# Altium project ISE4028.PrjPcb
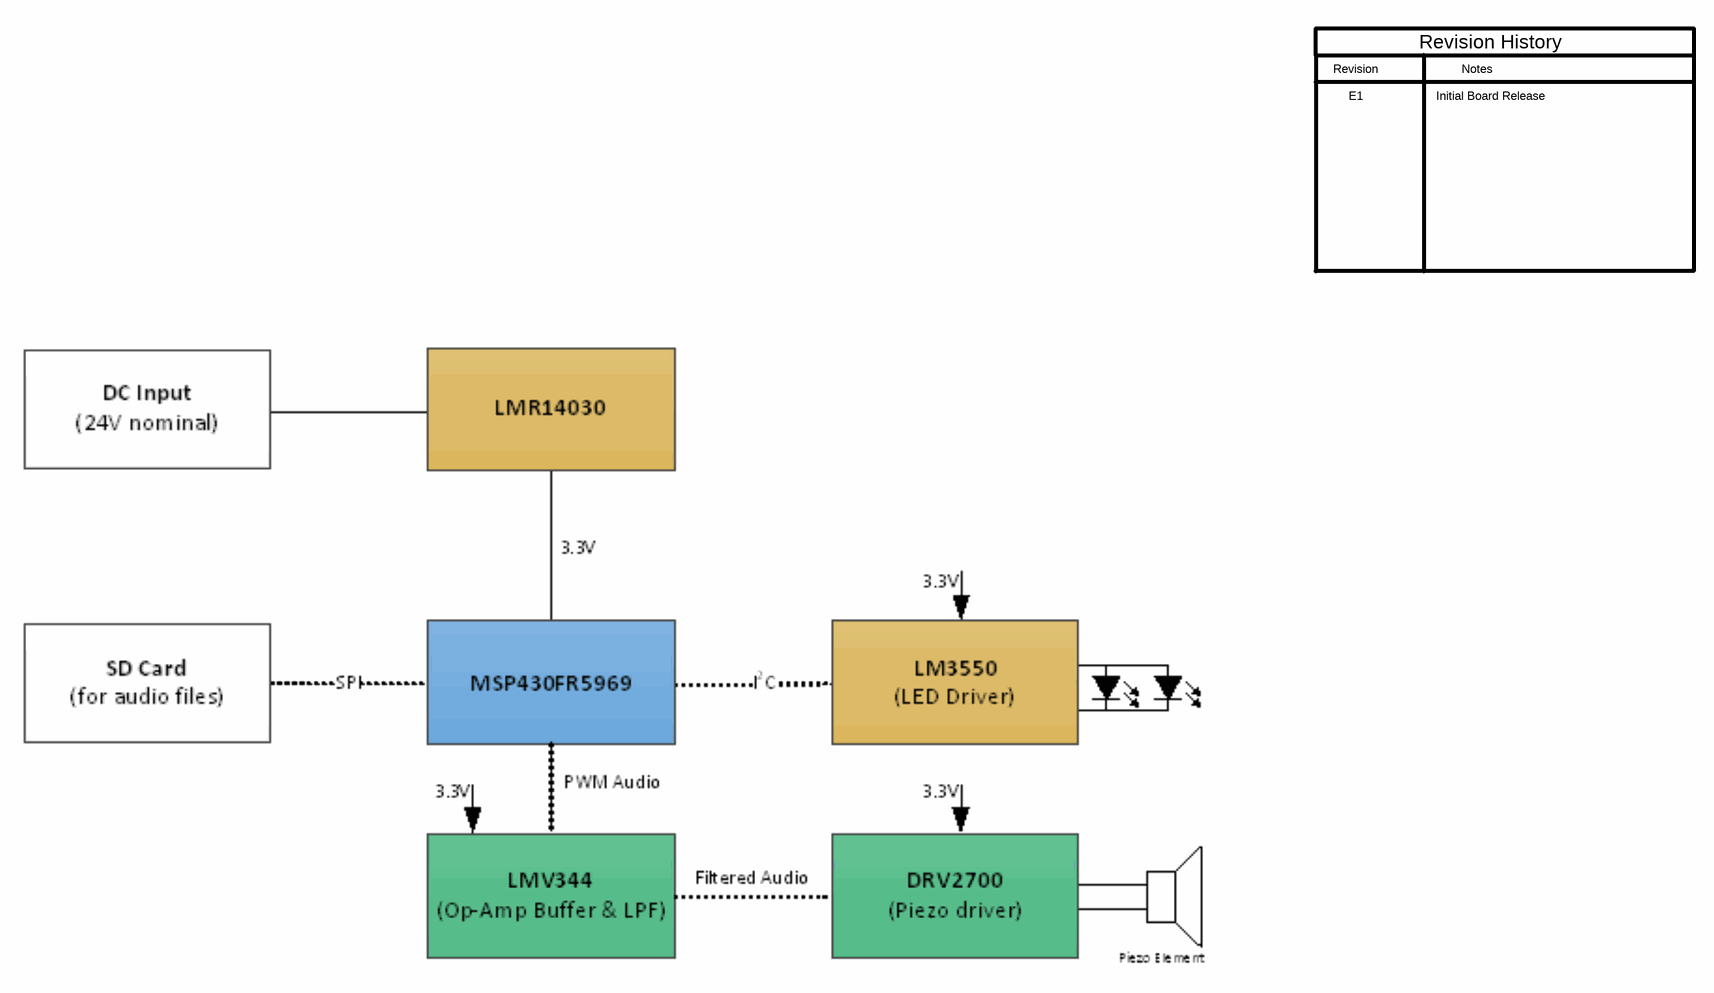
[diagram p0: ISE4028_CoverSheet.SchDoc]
CopyrightYear: 2015; EVM_Orderable: N/A; PCB_Rev: E1; PRJ_Customer: Public Release; PRJ_Engineer: Evan Cornell; PRJ_Number: ISE4028; PRJ_Title: Piezo Speaker Strobe Notification Reference Design for Fire Alarms; SCH_Rev: E1; TechSupport: http://www.ti.com/support; TID: TIDA-00376
4 sheets, 158 parts. Net scope: global (net labels, ports and power ports of the same name join across sheets).
Board file: ISE4028_TID.PcbDoc
Sheets:
  ISE4028_CoverSheet.SchDoc
  ISE4028_PWR_MCU.SchDoc
  ISE4028_PIEZO_LED.SchDoc
  ISE4028_TID_Hardware.SchDoc

## Sheet ISE4028_CoverSheet.SchDoc: CoverSheet
size 431 x 279 mm; Date: Not shown in title block; ApprovedBy: Not shown in title block; CheckedBy: Not shown in title block; Author: Not shown in title block; CompanyName: Not shown in title block; DrawnBy: Evan Cornell; Engineer: Not shown in title block; Organization: Not shown in title block; Address1: Not shown in title block; Address2: Not shown in title block; Address3: Not shown in title block; Address4: Not shown in title block; DocumentNumber: 1; Revision: Use project parameter SCH_Rev; SheetNumber: 1; SheetTotal: 4; PageSetup: Record=PageOptions¦CenterHorizontal=True¦CenterVertical=True¦PrintScale=1.00¦XCorrection=1.00¦YCorrection=1.00¦PrintKind=0¦BorderSize=5000000¦LeftOffset=0¦BottomOffset=0¦Orientation=2¦PaperLength=1000¦PaperWidth=1000¦Scale=100¦PaperSource=15¦PrintQuality=600¦MediaType=1¦DitherType=10¦PaperKind=Letter¦PrintScaleMode=1

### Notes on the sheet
- Revision
- Notes
- Revision History
- E1
- Initial Board Release

## Sheet ISE4028_PWR_MCU.SchDoc: PWR_MCU
size 431 x 279 mm; Date: Not shown in title block; ApprovedBy: Not shown in title block; CheckedBy: Not shown in title block; Author: Not shown in title block; CompanyName: Not shown in title block; DrawnBy: Evan Cornell; Engineer: Not shown in title block; Organization: Not shown in title block; Address1: Not shown in title block; Address2: Not shown in title block; Address3: Not shown in title block; Address4: Not shown in title block; DocumentNumber: 2; Revision: Use project parameter SCH_Rev; SheetNumber: 2; SheetTotal: 4; PageSetup: Record=PageOptions¦CenterHorizontal=True¦CenterVertical=True¦PrintScale=1.00¦XCorrection=1.00¦YCorrection=1.00¦PrintKind=0¦BorderSize=5000000¦LeftOffset=0¦BottomOffset=0¦Orientation=2¦PaperLength=1000¦PaperWidth=1000¦Scale=100¦PaperSource=15¦PrintQuality=600¦MediaType=1¦DitherType=10¦PaperKind=Letter¦PrintScaleMode=1
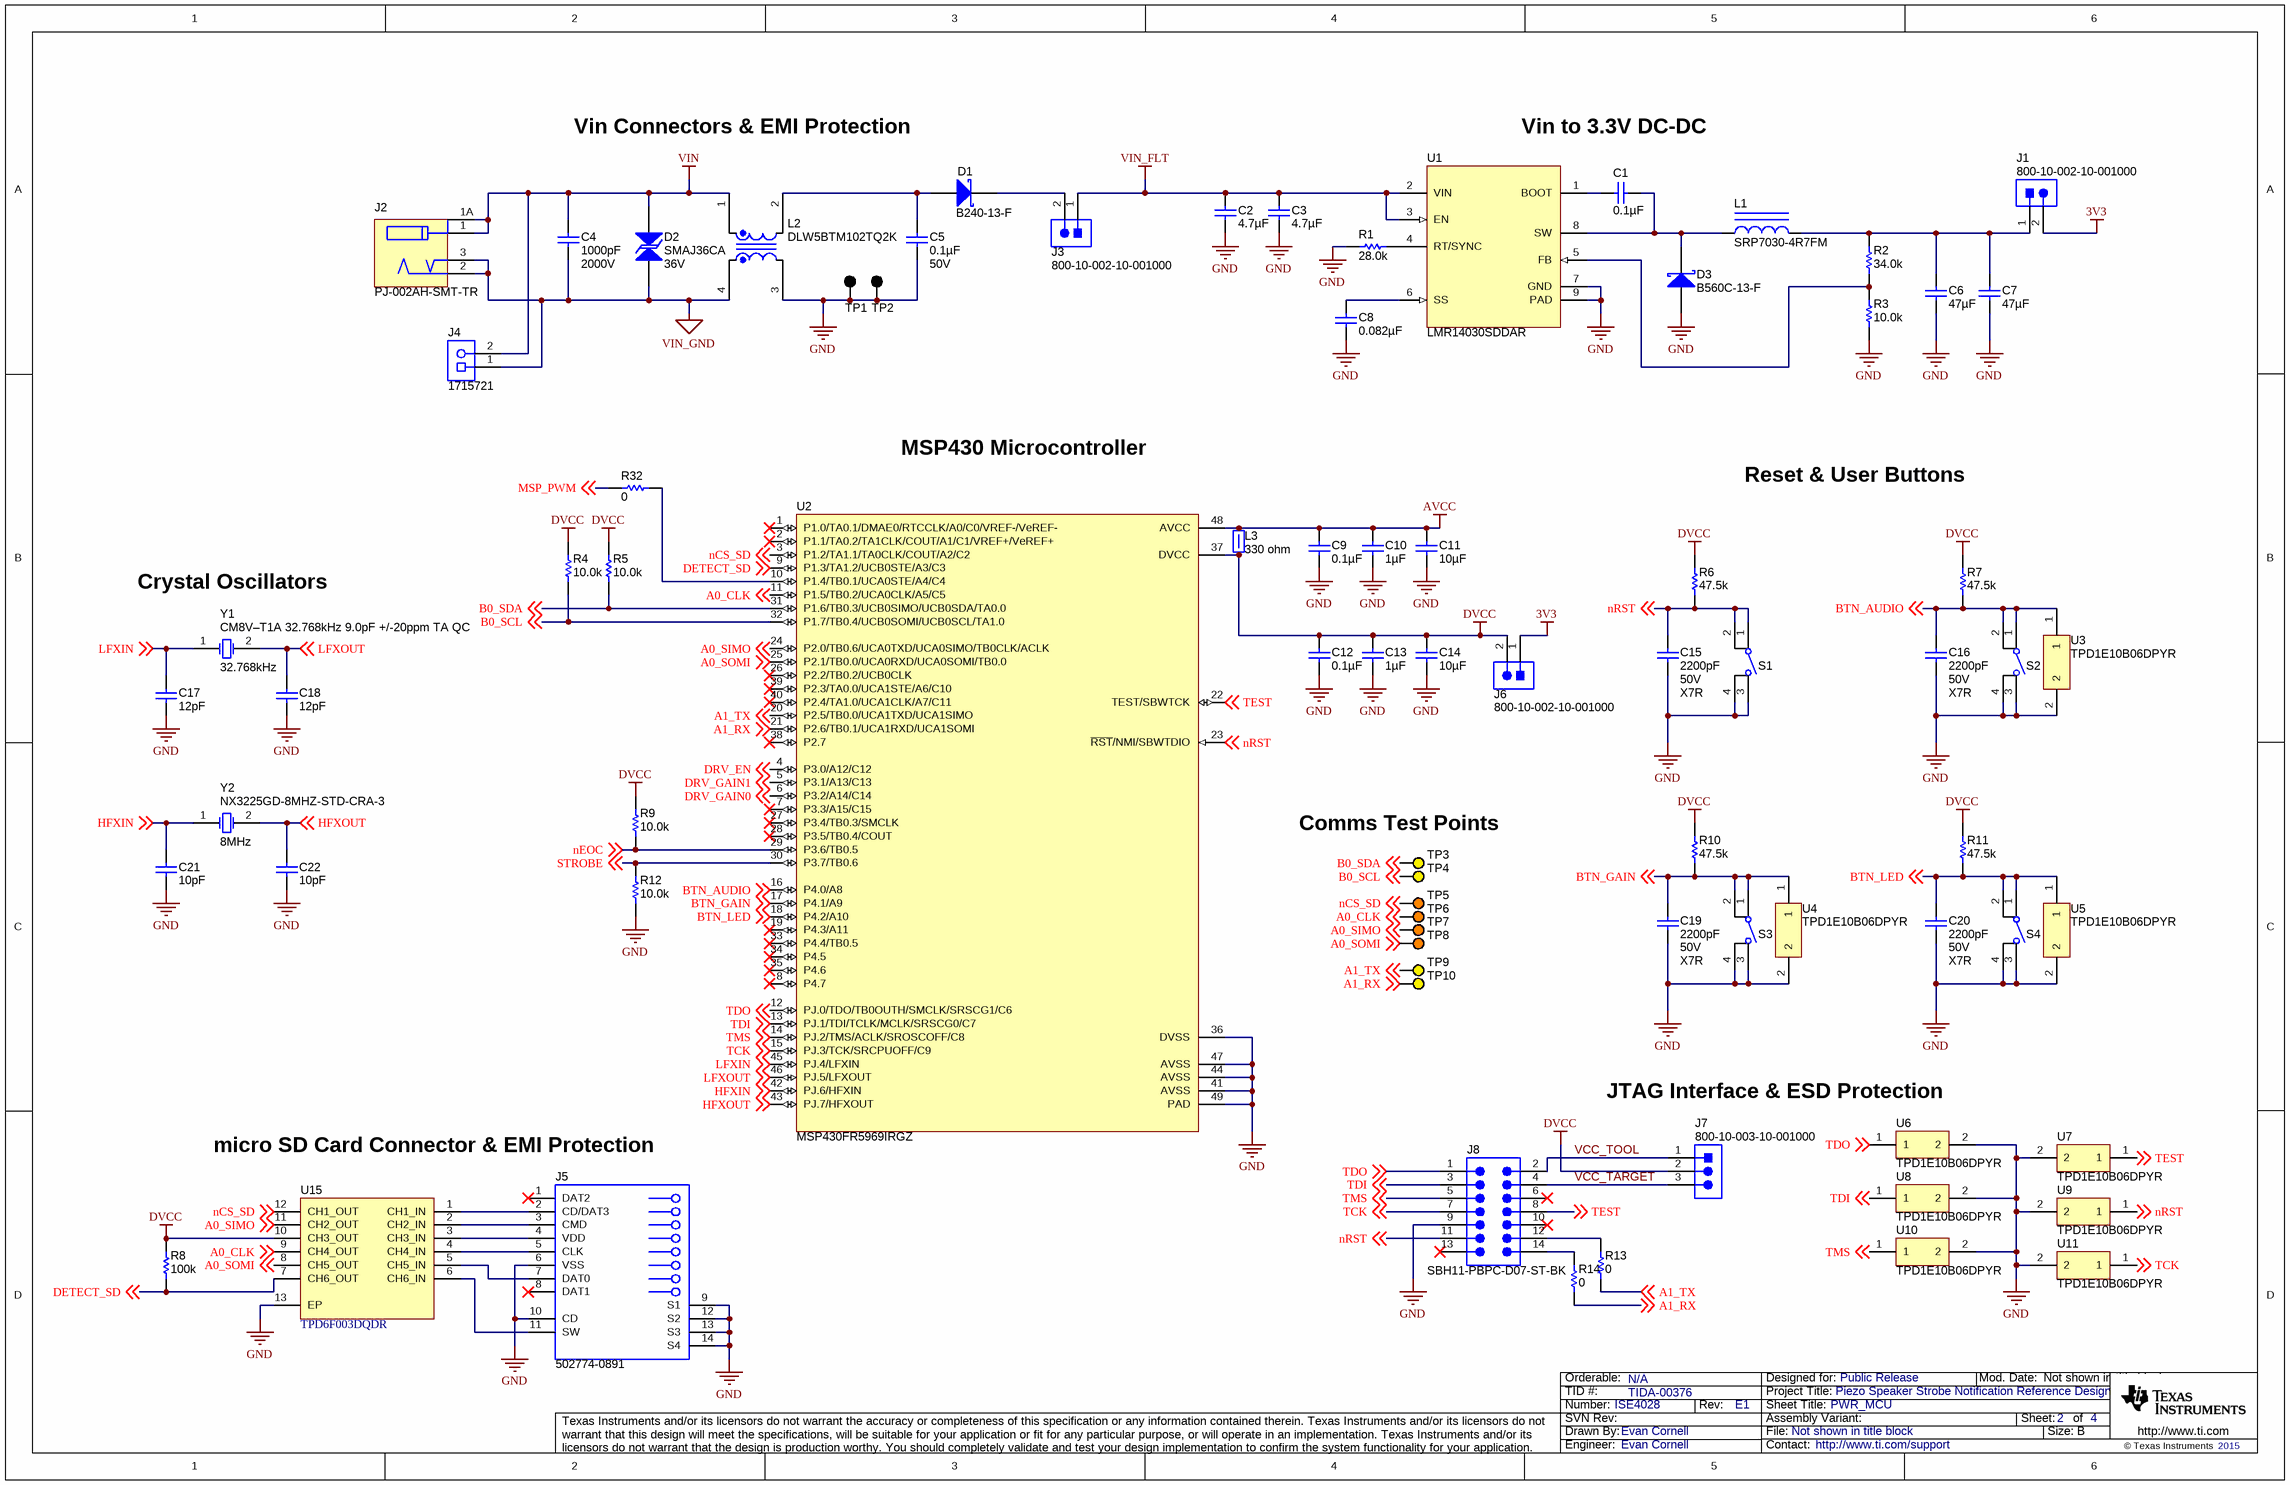
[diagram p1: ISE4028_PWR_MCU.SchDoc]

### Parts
C1  ValueDisplayed: 0.1µF  [0402]  (hidden comment: C1005X7R1H104K)
C2  ValueDisplayed: 4.7µF  [1206]  (hidden comment: GRM31CR71H475KA12L)
C3  ValueDisplayed: 4.7µF  [1206]  (hidden comment: GRM31CR71H475KA12L)
C4  ValueDisplayed: 1000pF  Value2: 2000V  [1210]  (hidden comment: C1210C102KGRACTU)
C5  ValueDisplayed: 0.1µF  Value2: 50V  [0402]  (hidden comment: C1005X7R1H104K)
C6  ValueDisplayed: 47µF  [1210]  (hidden comment: GRM32ER71A476KE15L)
C7  ValueDisplayed: 47µF  [1210]  (hidden comment: GRM32ER71A476KE15L)
C8  ValueDisplayed: 0.082µF  [0402]  (hidden comment: GRM155R71C823KA88D)
C9  ValueDisplayed: 0.1µF  [0402]  (hidden comment: GRM155R71C104KA88D)
C10  ValueDisplayed: 1µF  [0603]  (hidden comment: C1608X7R1C105K)
C11  ValueDisplayed: 10µF  [0805_HV]  (hidden comment: C2012X7R0J106M125AB)
C12  ValueDisplayed: 0.1µF  [0402]  (hidden comment: GRM155R71C104KA88D)
C13  ValueDisplayed: 1µF  [0603]  (hidden comment: C1608X7R1C105K)
C14  ValueDisplayed: 10µF  [0805_HV]  (hidden comment: C2012X7R0J106M125AB)
C15  ValueDisplayed: 2200pF  Value2: 50V  TempCo: X7R  [0402]  (hidden comment: C1005X7R1H222K)
C16  ValueDisplayed: 2200pF  Value2: 50V  TempCo: X7R  [0402]  (hidden comment: C1005X7R1H222K)
C17  ValueDisplayed: 12pF  [0402]  (hidden comment: GRM1555C1E120JA01D)
C18  ValueDisplayed: 12pF  [0402]  (hidden comment: GRM1555C1E120JA01D)
C19  ValueDisplayed: 2200pF  Value2: 50V  TempCo: X7R  [0402]  (hidden comment: C1005X7R1H222K)
C20  ValueDisplayed: 2200pF  Value2: 50V  TempCo: X7R  [0402]  (hidden comment: C1005X7R1H222K)
C21  ValueDisplayed: 10pF  [0402]  (hidden comment: GRM1555C1H100JA01D)
C22  ValueDisplayed: 10pF  [0402]  (hidden comment: GRM1555C1H100JA01D)
D1  B240-13-F  [SMB]
D2  SMAJ36CA  value 36V  [SMA]
D3  B560C-13-F  [SMC]
J1  800-10-002-10-001000  [Mill-Max_800-10-002-10-001000]
J2  PJ-002AH-SMT-TR  [CUI_PJ-002AH-SMT]
J3  800-10-002-10-001000  [Mill-Max_800-10-002-10-001000]
J4  1715721  [PhoenixContact_1715721]
J5  502774-0891  [Molex_502774-0891]
J6  800-10-002-10-001000  [Mill-Max_800-10-002-10-001000]
J7  800-10-003-10-001000  [Mill-Max_800-10-003-10-001000]
J8  SBH11-PBPC-D07-ST-BK  [CONN_SBH11-PBPC-D07-ST-BK]
L1  SRP7030-4R7FM  [SRP7030F_3]
L2  DLW5BTM102TQ2K  [DLW5BT_TQ2]
L3  value 330 ohm  [0603]  (hidden comment: BLM18SG331TN1D)
R1  ValueDisplayed: 28.0k  [0402]  (hidden comment: CRCW040228K0FKED)
R2  ValueDisplayed: 34.0k  [0402]  (hidden comment: CRCW040234K0FKED)
R3  ValueDisplayed: 10.0k  [0402]  (hidden comment: CRCW040210K0FKED)
R4  ValueDisplayed: 10.0k  [0402]  (hidden comment: CRCW040210K0FKED)
R5  ValueDisplayed: 10.0k  [0402]  (hidden comment: CRCW040210K0FKED)
R6  value 47.5k  [0603]  (hidden comment: CRCW060347K5FKEA)
R7  value 47.5k  [0603]  (hidden comment: CRCW060347K5FKEA)
R8  ValueDisplayed: 100k  [0402]  (hidden comment: CRCW0402100KFKED)
R9  ValueDisplayed: 10.0k  [0402]  (hidden comment: CRCW040210K0FKED)
R10  value 47.5k  [0603]  (hidden comment: CRCW060347K5FKEA)
R11  value 47.5k  [0603]  (hidden comment: CRCW060347K5FKEA)
R12  ValueDisplayed: 10.0k  [0402]  (hidden comment: CRCW040210K0FKED)
R13  value 0  [0402]  (hidden comment: CRCW04020000Z0ED)
R14  value 0  [0402]  (hidden comment: CRCW04020000Z0ED)
R32  value 0  [0402]  (hidden comment: CRCW04020000Z0ED)
S1  4-1437565-1  [SW_FSM4JSMA]  (value not drawn)
S2  4-1437565-1  [SW_FSM4JSMA]  (value not drawn)
S3  4-1437565-1  [SW_FSM4JSMA]  (value not drawn)
S4  4-1437565-1  [SW_FSM4JSMA]  (value not drawn)
TP1  5001  [Keystone5001]  (value not drawn)
TP2  5001  [Keystone5001]  (value not drawn)
TP3  5004  [Keystone5004]  (value not drawn)
TP4  5004  [Keystone5004]  (value not drawn)
TP5  5003  [Keystone5003]  (value not drawn)
TP6  5003  [Keystone5003]  (value not drawn)
TP7  5003  [Keystone5003]  (value not drawn)
TP8  5003  [Keystone5003]  (value not drawn)
TP9  5004  [Keystone5004]  (value not drawn)
TP10  5004  [Keystone5004]  (value not drawn)
U1  LMR14030SDDAR  [DDA0008E_N]
U2  MSP430FR5969IRGZ  [RGZ0048B]
U3  TPD1E10B06DPYR  [DPY0002A]
U4  TPD1E10B06DPYR  [DPY0002A]
U5  TPD1E10B06DPYR  [DPY0002A]
U6  TPD1E10B06DPYR  [DPY0002A]
U7  TPD1E10B06DPYR  [DPY0002A]
U8  TPD1E10B06DPYR  [DPY0002A]
U9  TPD1E10B06DPYR  [DPY0002A]
U10  TPD1E10B06DPYR  [DPY0002A]
U11  TPD1E10B06DPYR  [DPY0002A]
U15  TPD6F003DQDR  [DQD0012A]
Y1  CM8V–T1A 32.768kHz 9.0pF +/-20ppm TA QC  Frequency: 32.768kHz  [MC_CM8V-T1A]
Y2  NX3225GD-8MHZ-STD-CRA-3  Frequency: 8MHz  [NDK_NX3225GD]

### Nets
3V3: J1.2 J6.1
AVCC: C9.2 C10.2 C11.1 L3.2 U2.48(AVCC)
DVCC: C12.2 C13.2 C14.1 J6.2 J7.2 L3.1 R4.2 R5.2 R6.2 R7.2 R8.2 R9.2 R10.2 R11.2 U2.37(DVCC) U15.10(CH3_OUT)
GND: C2.2 C3.2 C5.2 C6.2 C7.2 C8.2 C9.1 C10.1 C11.2 C12.1 C13.1 C14.2 C15.2 C16.2 C17.2 C18.2 C19.2 C20.2 C21.2 C22.2 D3.2(A) J5.6(VSS) J5.9(S1) J5.10(CD) J5.12(S2) J5.13(S3) J5.14(S4) J8.9 L2.3 R1.2 R3.1 R12.1 S1.3 S1.4 S2.3 S2.4 S3.3 S3.4 S4.3 S4.4 TP1.1 TP2.1 U1.7(GND) U1.9(PAD) U2.36(DVSS) U2.41(AVSS) U2.44(AVSS) U2.47(AVSS) U2.49(PAD) U3.2 U4.2 U5.2 U6.2 U7.2 U8.2 U9.2 U10.2 U11.2 U15.13(EP)
VIN: C4.2 D2.2 J2.1 J2.1A J4.2 L2.1
VIN_FLT: C2.1 C3.1 J3.1 U1.2(VIN) U1.3(EN)
VIN_GND: C4.1 D2.1 J2.2 J2.3 J4.1 L2.4
A0_CLK: TP6.1 U2.11(P1.5/TB0.2/UCA0CLK/A5/C5) U15.9(CH4_OUT) ; off-sheet A0_CLK
A0_SIMO: TP7.1 U2.24(P2.0/TB0.6/UCA0TXD/UCA0SIMO/TB0CLK/ACLK) U15.11(CH2_OUT) ; off-sheet A0_SIMO
A0_SOMI: TP8.1 U2.25(P2.1/TB0.0/UCA0RXD/UCA0SOMI/TB0.0) U15.8(CH5_OUT) ; off-sheet A0_SOMI
A1_RX: R14.1 TP10.1 U2.21(P2.6/TB0.1/UCA1RXD/UCA1SOMI) ; off-sheet A1_RX
A1_TX: R13.1 TP9.1 U2.20(P2.5/TB0.0/UCA1TXD/UCA1SIMO) ; off-sheet A1_TX
B0_SCL: R4.1 TP4.1 U2.32(P1.7/TB0.4/UCB0SOMI/UCB0SCL/TA1.0) ; off-sheet B0_SCL
B0_SDA: R5.1 TP3.1 U2.31(P1.6/TB0.3/UCB0SIMO/UCB0SDA/TA0.0) ; off-sheet B0_SDA
BTN_AUDIO: C16.1 R7.1 S2.1 S2.2 U2.16(P4.0/A8) U3.1 ; off-sheet BTN_AUDIO
BTN_GAIN: C19.1 R10.1 S3.1 S3.2 U2.17(P4.1/A9) U4.1 ; off-sheet BTN_GAIN
BTN_LED: C20.1 R11.1 S4.1 S4.2 U2.18(P4.2/A10) U5.1 ; off-sheet BTN_LED
DETECT_SD: R8.1 U2.9(P1.3/TA1.2/UCB0STE/A3/C3) U15.7(CH6_OUT) ; off-sheet DETECT_SD
DRV_EN: U2.4(P3.0/A12/C12) ; off-sheet DRV_EN
DRV_GAIN0: U2.6(P3.2/A14/C14) ; off-sheet DRV_GAIN0
DRV_GAIN1: U2.5(P3.1/A13/C13) ; off-sheet DRV_GAIN1
HFXIN: C21.1 U2.42(PJ.6/HFXIN) Y2.1(OSC1) ; off-sheet HFXIN
HFXOUT: C22.1 U2.43(PJ.7/HFXOUT) Y2.2(OSC2) ; off-sheet HFXOUT
LFXIN: C17.1 U2.45(PJ.4/LFXIN) Y1.1(OSC1) ; off-sheet LFXIN
LFXOUT: C18.1 U2.46(PJ.5/LFXOUT) Y1.2(OSC2) ; off-sheet LFXOUT
MSP_PWM: R32.2 ; off-sheet MSP_PWM
nCS_SD: TP5.1 U2.3(P1.2/TA1.1/TA0CLK/COUT/A2/C2) U15.12(CH1_OUT) ; off-sheet nCS_SD
nEOC: R9.1 U2.29(P3.6/TB0.5) ; off-sheet nEOC
nRST: C15.1 J8.11 R6.1 S1.1 S1.2 U2.23(~{RST}/NMI/SBWTDIO) U9.1 ; off-sheet nRST
STROBE: R12.2 U2.30(P3.7/TB0.6) ; off-sheet STROBE
TCK: J8.7 U2.15(PJ.3/TCK/SRCPUOFF/C9) U11.1 ; off-sheet TCK
TDI: J8.3 U2.13(PJ.1/TDI/TCLK/MCLK/SRSCG0/C7) U8.1 ; off-sheet TDI
TDO: J8.1 U2.12(PJ.0/TDO/TB0OUTH/SMCLK/SRSCG1/C6) U6.1 ; off-sheet TDO
TEST: J8.8 U2.22(TEST/SBWTCK) U7.1 ; off-sheet TEST
TMS: J8.5 U2.14(PJ.2/TMS/ACLK/SROSCOFF/C8) U10.1 ; off-sheet TMS
VCC_TARGET: J7.3 J8.4
VCC_TOOL: J7.1 J8.2
NetC1_1: C1.1 D3.1(K) L1.1 U1.8(SW)
NetC1_2: C1.2 U1.1(BOOT)
NetC5_1: C5.1 D1.2(A) L2.2
NetC6_1: C6.1 C7.1 J1.1 L1.2 R2.2
NetC8_1: C8.1 U1.6(SS)
NetD1_1: D1.1(K) J3.2
NetJ5_2: J5.2(CD/DAT3) U15.1(CH1_IN)
NetJ5_3: J5.3(CMD) U15.2(CH2_IN)
NetJ5_4: J5.4(VDD) U15.3(CH3_IN)
NetJ5_5: J5.5(CLK) U15.4(CH4_IN)
NetJ5_7: J5.7(DAT0) U15.5(CH5_IN)
NetJ5_11: J5.11(SW) U15.6(CH6_IN)
NetJ8_12: J8.12 R13.2
NetJ8_14: J8.14 R14.2
NetR1_1: R1.1 U1.4(RT/SYNC)
NetR2_1: R2.1 R3.2 U1.5(FB)
NetR32_1: R32.1 U2.10(P1.4/TB0.1/UCA0STE/A4/C4)

Not connected (* = marked no-connect by the designer): J5 1(DAT2)* 8(DAT1)*; J8 6* 10* 13*; U2 1(P1.0/TA0.1/DMAE0/RTCCLK/A0/C0/VREF-/VeREF-)* 2(P1.1/TA0.2/TA1CLK/COUT/A1/C1/VREF+/VeREF+)* 7(P3.3/A15/C15)* 8(P4.7)* 19(P4.3/A11)* 26(P2.2/TB0.2/UCB0CLK)* 27(P3.4/TB0.3/SMCLK)* 28(P3.5/TB0.4/COUT)* 33(P4.4/TB0.5)* 34(P4.5)* 35(P4.6)* 38(P2.7)* 39(P2.3/TA0.0/UCA1STE/A6/C10)* 40(P2.4/TA1.0/UCA1CLK/A7/C11)*

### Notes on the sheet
- Vin Connectors & EMI Protection
- Vin to 3.3V DC-DC
- MSP430 Microcontroller
- Reset & User Buttons
- Crystal Oscillators
- Comms Test Points
- JTAG Interface & ESD Protection
- micro SD Card Connector & EMI Protection

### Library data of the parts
C1 = C1005X7R1H104K: CAP, CERM, 0.1 µF, 50 V, +/- 10%, X7R, 0402; Manufacturer: TDK; Polarized: N; CompType: Capacitor; Value: 0.1uF; U/M: EA; Cap_F: 0.0000001; Tolerance_%: 10; Value1: Unknown; VDC_V: 50; Value2: 50V; TaMin_C: -55; TaMax_C: 125
C2 C3 = GRM31CR71H475KA12L: CAP, CERM, 4.7 µF, 50 V, +/- 10%, X7R, 1206; Manufacturer: MuRata; Polarized: N; CompType: Capacitor; Value: 4.7uF; U/M: EA; Cap_F: 0.0000047; Tolerance_%: 10; Value1: Unknown; VDC_V: 50; Value2: 50V; TaMin_C: -55; TaMax_C: 125; Cap_Case: 2220
C4 = C1210C102KGRACTU: CAP, CERM, 1000 pF, 2000 V, +/- 10%, X7R, 1210; Manufacturer: Kemet; Polarized: N; CompType: Capacitor; Value: 1000pF; U/M: EA; Cap_F: 0.000000001; Tolerance_%: 10; Value1: Unknown; VDC_V: 2000; TaMin_C: -55; TaMax_C: 125
C5 = C1005X7R1H104K: CAP, CERM, 0.1 µF, 50 V, +/- 10%, X7R, 0402; Manufacturer: TDK; Polarized: N; CompType: Capacitor; Value: 0.1uF; U/M: EA; Cap_F: 0.0000001; Tolerance_%: 10; Value1: Unknown; VDC_V: 50; TaMin_C: -55; TaMax_C: 125
C6 C7 = GRM32ER71A476KE15L: CAP, CERM, 47 µF, 10 V, +/- 10%, X7R, 1210; Manufacturer: MuRata; Polarized: N; CompType: Capacitor; Value: 47uF; U/M: EA; Cap_F: 0.000047; Tolerance_%: 10; Value1: Unknown; Value2: 10V; TaMin_C: -55; TaMax_C: 125
C8 = GRM155R71C823KA88D: CAP, CERM, 0.082 µF, 16 V, +/- 10%, X7R, 0402; Manufacturer: MuRata; Polarized: N; CompType: Capacitor; Value: 0.082uF; U/M: EA; Cap_F: 0.000000082; Tolerance_%: 10; Value1: Unknown; VDC_V: 16; Value2: 16V; TaMin_C: -55; TaMax_C: 125
C9 C12 = GRM155R71C104KA88D: CAP, CERM, 0.1uF, 16V, +/-10%, X7R, 0402; Manufacturer: MuRata; Polarized: N; CompType: Capacitor; U/M: EA; Cap_F: 0.0000001; Tolerance_%: 10; Value1: Unknown; VDC_V: 16; TaMin_C: -55; TaMax_C: 125
C10 C13 = C1608X7R1C105K: CAP, CERM, 1uF, 16V, +/-10%, X7R, 0603; Manufacturer: TDK; Polarized: N; CompType: Capacitor; U/M: EA; Cap_F: 0.000001; Tolerance_%: 10; ESR_Ohm: 0.0057; Value1: 0.0057 ohm; VDC_V: 16; TaMin_C: -55; TaMax_C: 125
C11 C14 = C2012X7R0J106M125AB: CAP, CERM, 10 µF, 6.3 V, +/- 20%, X7R, 0805; Manufacturer: TDK; Polarized: N; CompType: Capacitor; Value: 10uF; U/M: EA; Cap_F: 0.00001; Tolerance_%: 20; Value1: Unknown; VDC_V: 6.3; Value2: 6.3V; TaMin_C: -55; TaMax_C: 125; Cap_Case: 0805
C15 C16 C19 C20 = C1005X7R1H222K: CAP, CERM, 2200pF, 50V, +/-10%, X7R, 0402; Manufacturer: TDK; Polarized: N; CompType: Capacitor; U/M: EA; Cap_F: 0.0000000022; Tolerance_%: 10; ESR_Ohm: 0.1433; Value1: 0.1433 ohm; VDC_V: 50; TaMin_C: -55; TaMax_C: 125
C17 C18 = GRM1555C1E120JA01D: CAP, CERM, 12 pF, 25 V, +/- 5%, C0G/NP0, 0402; Manufacturer: MuRata; Polarized: N; CompType: Capacitor; Value: 12pF; U/M: EA; Cap_F: 0.000000000012; Tolerance_%: 5; Value1: Unknown; VDC_V: 25; Value2: 25V; TaMin_C: -55; TaMax_C: 125
C21 C22 = GRM1555C1H100JA01D: CAP, CERM, 10 pF, 50 V, +/- 5%, C0G/NP0, 0402; Manufacturer: MuRata; Polarized: N; CompType: Capacitor; Value: 10pF; U/M: EA; Cap_F: 0.00000000001; Tolerance_%: 5; Value1: Unknown; VDC_V: 50; Value2: 50V; TaMin_C: -55; TaMax_C: 125
D1 = B240-13-F: Diode, Schottky, 40 V, 2 A, SMB; Manufacturer: Diodes Inc.; U/M: EA; Vf_V: 0.5; Value: 40V; Value1: 2A; Value2: 0.5V; Io_A: 2; Vr_V: 40; TJmax_C: 150; RJC_CperW: 20
D2 = SMAJ36CA: Diode, TVS, Bi, 36 V, 400 W, SMA; Manufacturer: Littelfuse; U/M: EA; Power_W: 400; Vr_V: 36; Value1: 400W; RJA_CperW: 120
D3 = B560C-13-F: Diode, Schottky, 60 V, 5 A, SMC; Manufacturer: Diodes Inc.; U/M: EA; Vf_V: 0.7; Value: 60V; Value1: 5A; Value2: 0.7V; Io_A: 5; Vr_V: 60; TJmax_C: 125; RJC_CperW: 10
J1 J3 J6 = 800-10-002-10-001000: Header, 100mil, 2x1, TH; Manufacturer: Mill-Max; SymbolCreator: a0412235; U/M: EA
J2 = PJ-002AH-SMT-TR: Power Jack, SMT; Manufacturer: CUI Inc.; SymbolCreator: a0411947; U/M: EA
J4 = 1715721: Conn Term Block, 2POS, 5.08mm, TH; Manufacturer: Phoenix Contact; SymbolCreator: a0412235; CompType: Terminal Block; U/M: EA; Value: 2x1
J5 = 502774-0891: Conncetor, micro SD Card, 1.1 mm, R/A, SMT; Manufacturer: Molex; SymbolCreator: Altium; CompType: Connector; U/M: EA
J7 = 800-10-003-10-001000: Header, 3x1, 100mil, SMT; Manufacturer: Mill-Max; SymbolCreator: a0799628; U/M: EA
J8 = SBH11-PBPC-D07-ST-BK: Header (shrouded), 100 mil, 7x2, Gold plated, TH; Manufacturer: Sullins Connector Solutions; SymbolCreator: a0412235; CompType: Connector; U/M: EA
L1 = SRP7030-4R7FM: Inductor, Flat Wire, Powdered Iron, 4.7 µH, 5 A, 0.035 ohm, SMD; Manufacturer: Bourns; Value: 4.7uH; Ind_H: 4.7E-6; ValueDisplayed: 4.7µH; Imax_A: 5; Irms: 5A @ 40C rise; Isat: 7A @ 20% inductance drop; DCR_ohm: 0.035; Value2: 5A
L2 = DLW5BTM102TQ2K: Coupled inductor, 2.5 A, 0.034 ohm, SMD; Manufacturer: MuRata; SymbolCreator: a0412235; Isat: 2.5; DCR_ohm: 0.034
L3 = BLM18SG331TN1D: 1.5A Ferrite Bead, 330 ohm @ 100MHz, SMD; Manufacturer: MuRata; Imax_A: 1.5; DCR_ohm: 0.07; Value1: 0.07 ohm; ZTyp@100MHz_Ohm: 330; U/M: EA
R1 = CRCW040228K0FKED: RES, 28.0 k, 1%, 0.063 W, 0402; Manufacturer: Vishay-Dale; CompType: Resistor; Value: 28.0k; Res_ohm: 28000; Value_Code: 28k0; Tolerance_%: 1; Power_W: 0.063; Value2: 0.063W; VDC_V: 50; TempCo: 100 ppm/C; EIA_Code: E96; U/M: EA
R2 = CRCW040234K0FKED: RES, 34.0 k, 1%, 0.063 W, 0402; Manufacturer: Vishay-Dale; CompType: Resistor; Value: 34.0k; Res_ohm: 34000; Value_Code: 34k0; Tolerance_%: 1; Power_W: 0.063; Value2: 0.063W; VDC_V: 50; TempCo: 100 ppm/C; EIA_Code: E96; U/M: EA
R3-R5 R9 R12 = CRCW040210K0FKED: RES, 10.0 k, 1%, 0.063 W, 0402; Manufacturer: Vishay-Dale; CompType: Resistor; Value: 10.0k; Res_ohm: 10000; Value_Code: 10k0; Tolerance_%: 1; Power_W: 0.063; Value2: 0.063W; VDC_V: 50; TempCo: 100 ppm/C; EIA_Code: E96; U/M: EA
R6 R7 R10 R11 = CRCW060347K5FKEA: RES, 47.5k ohm, 1%, 0.1W, 0603; Manufacturer: Vishay-Dale; CompType: Resistor; Res_ohm: 47500; Value_Code: 47k5; Tolerance_%: 1; Power_W: 0.1; VDC_V: 75; TempCo: 100 ppm/C; EIA_Code: E96; U/M: EA
R8 = CRCW0402100KFKED: RES, 100 k, 1%, 0.063 W, 0402; Manufacturer: Vishay-Dale; CompType: Resistor; Value: 100k; Res_ohm: 100000; Tolerance_%: 1; Power_W: 0.063; Value2: 0.063W; VDC_V: 50; TempCo: 100 ppm/C; EIA_Code: E96; U/M: EA
R13 R14 R32 = CRCW04020000Z0ED: RES, 0 ohm, 5%, 0.063W, 0402; Manufacturer: Vishay-Dale; CompType: Resistor; Value_Code: 0000; Tolerance_%: 5; Power_W: 0.063; VDC_V: 50; TempCo: 200 ppm/C; EIA_Code: E24; U/M: EA
S1-S4 = 4-1437565-1: Switch, Tactile, SPST-NO, 0.05A, 12V, SMT; Manufacturer: TE Connectivity; SymbolCreator: a0412235; VDC_V: 12; SwitchFunction: Off-Mom; PositionCount: 1; CurrentRating_mA: 50
TP1 TP2 = 5001: Test Point, Miniature, Black, TH; Manufacturer: Keystone; CompType: Test Point Loop; U/M: EA
TP3 TP4 TP9 TP10 = 5004: Test Point, Miniature, Yellow, TH; Manufacturer: Keystone; CompType: Test Point Loop; U/M: EA
TP5-TP8 = 5003: Test Point, Miniature, Orange, TH; Manufacturer: Keystone; CompType: Test Point Loop; U/M: EA
U1 = LMR14030SDDAR: 40 V, 3.5 A Simple Switcher, 2.2 Mhz Step-Down Regulator with 40 uA Quiescent Current, DDA0008E; Alternate PartNumber: LMR14030SDDAT; Manufacturer: Texas Instruments; SymbolCreator: Altium; CompType: IC; U/M: EA
U2 = MSP430FR5969IRGZ: Mixed Signal Microcontroller, RGZ0048B; Manufacturer: Texas Instruments; SymbolCreator: a0411947; CompType: IC; U/M: EA
U3-U11 = TPD1E10B06DPYR: ESD in 0402 Package with 10 pF Capacitance and 6 V Breakdown, 1 Channel, -40 to +125 degC, 2-pin X2SON (DPY), Green (RoHS & no Sb/Br); Manufacturer: Texas Instruments; Alternate Manufacturer: None; Alternate PartNumber: Equivalent; Breakdown Voltage(Min)(V): 6; Eco-Plan: TBD; IEC 61000-4-2 Air-Gap(+/- kV): 30; IO Capacitance(Typ)(pF): 10; SubFamily: ESD Solution
U15 = TPD6F003DQDR: EMI Filter for Display Interface, 6 Channels, -40 to +85 degC, 12-pin WSON (DQD), Green (RoHS & no Sb/Br); Manufacturer: Texas Instruments; Alternate Manufacturer: None; Alternate PartNumber: Equivalent; Breakdown Voltage(Min)(V): 6; Ctotal(Typ)(pF): 19; IEC 61000-4-2 Air-Gap(Typ)(+/- kV): 20; IEC 61000-4-2 Contact(Typ)(+/- kV): 12; SubFamily: EMI Solution
Y1 = CM8V–T1A 32.768kHz 9.0pF +/-20ppm TA QC: Tuning Fork Crystal, 32.768kHz, 9pf, SMD; Manufacturer: Micro Crystal AG; SymbolCreator: a0412235; U/M: EA; TaMin_C: -40; TaMax_C: 85
Y2 = NX3225GD-8MHZ-STD-CRA-3: Crystal, 8MHz, 5pF, SMD; Manufacturer: NDK; SymbolCreator: a0412235; U/M: EA; TaMin_C: -40; TaMax_C: 150; Frequency Stability: ±150ppm

## Sheet ISE4028_PIEZO_LED.SchDoc: PIEZO_LED
size 431 x 279 mm; Date: Not shown in title block; ApprovedBy: Not shown in title block; CheckedBy: Not shown in title block; Author: Not shown in title block; CompanyName: Not shown in title block; DrawnBy: Evan Cornell; Engineer: Not shown in title block; Organization: Not shown in title block; Address1: Not shown in title block; Address2: Not shown in title block; Address3: Not shown in title block; Address4: Not shown in title block; DocumentNumber: 3; Revision: Use project parameter SCH_Rev; SheetNumber: 3; SheetTotal: 4; PageSetup: Record=PageOptions¦CenterHorizontal=True¦CenterVertical=True¦PrintScale=1.00¦XCorrection=1.00¦YCorrection=1.00¦PrintKind=0¦BorderSize=5000000¦LeftOffset=0¦BottomOffset=0¦Orientation=2¦PaperLength=1000¦PaperWidth=1000¦Scale=100¦PaperSource=15¦PrintQuality=600¦MediaType=1¦DitherType=10¦PaperKind=Letter¦PrintScaleMode=1
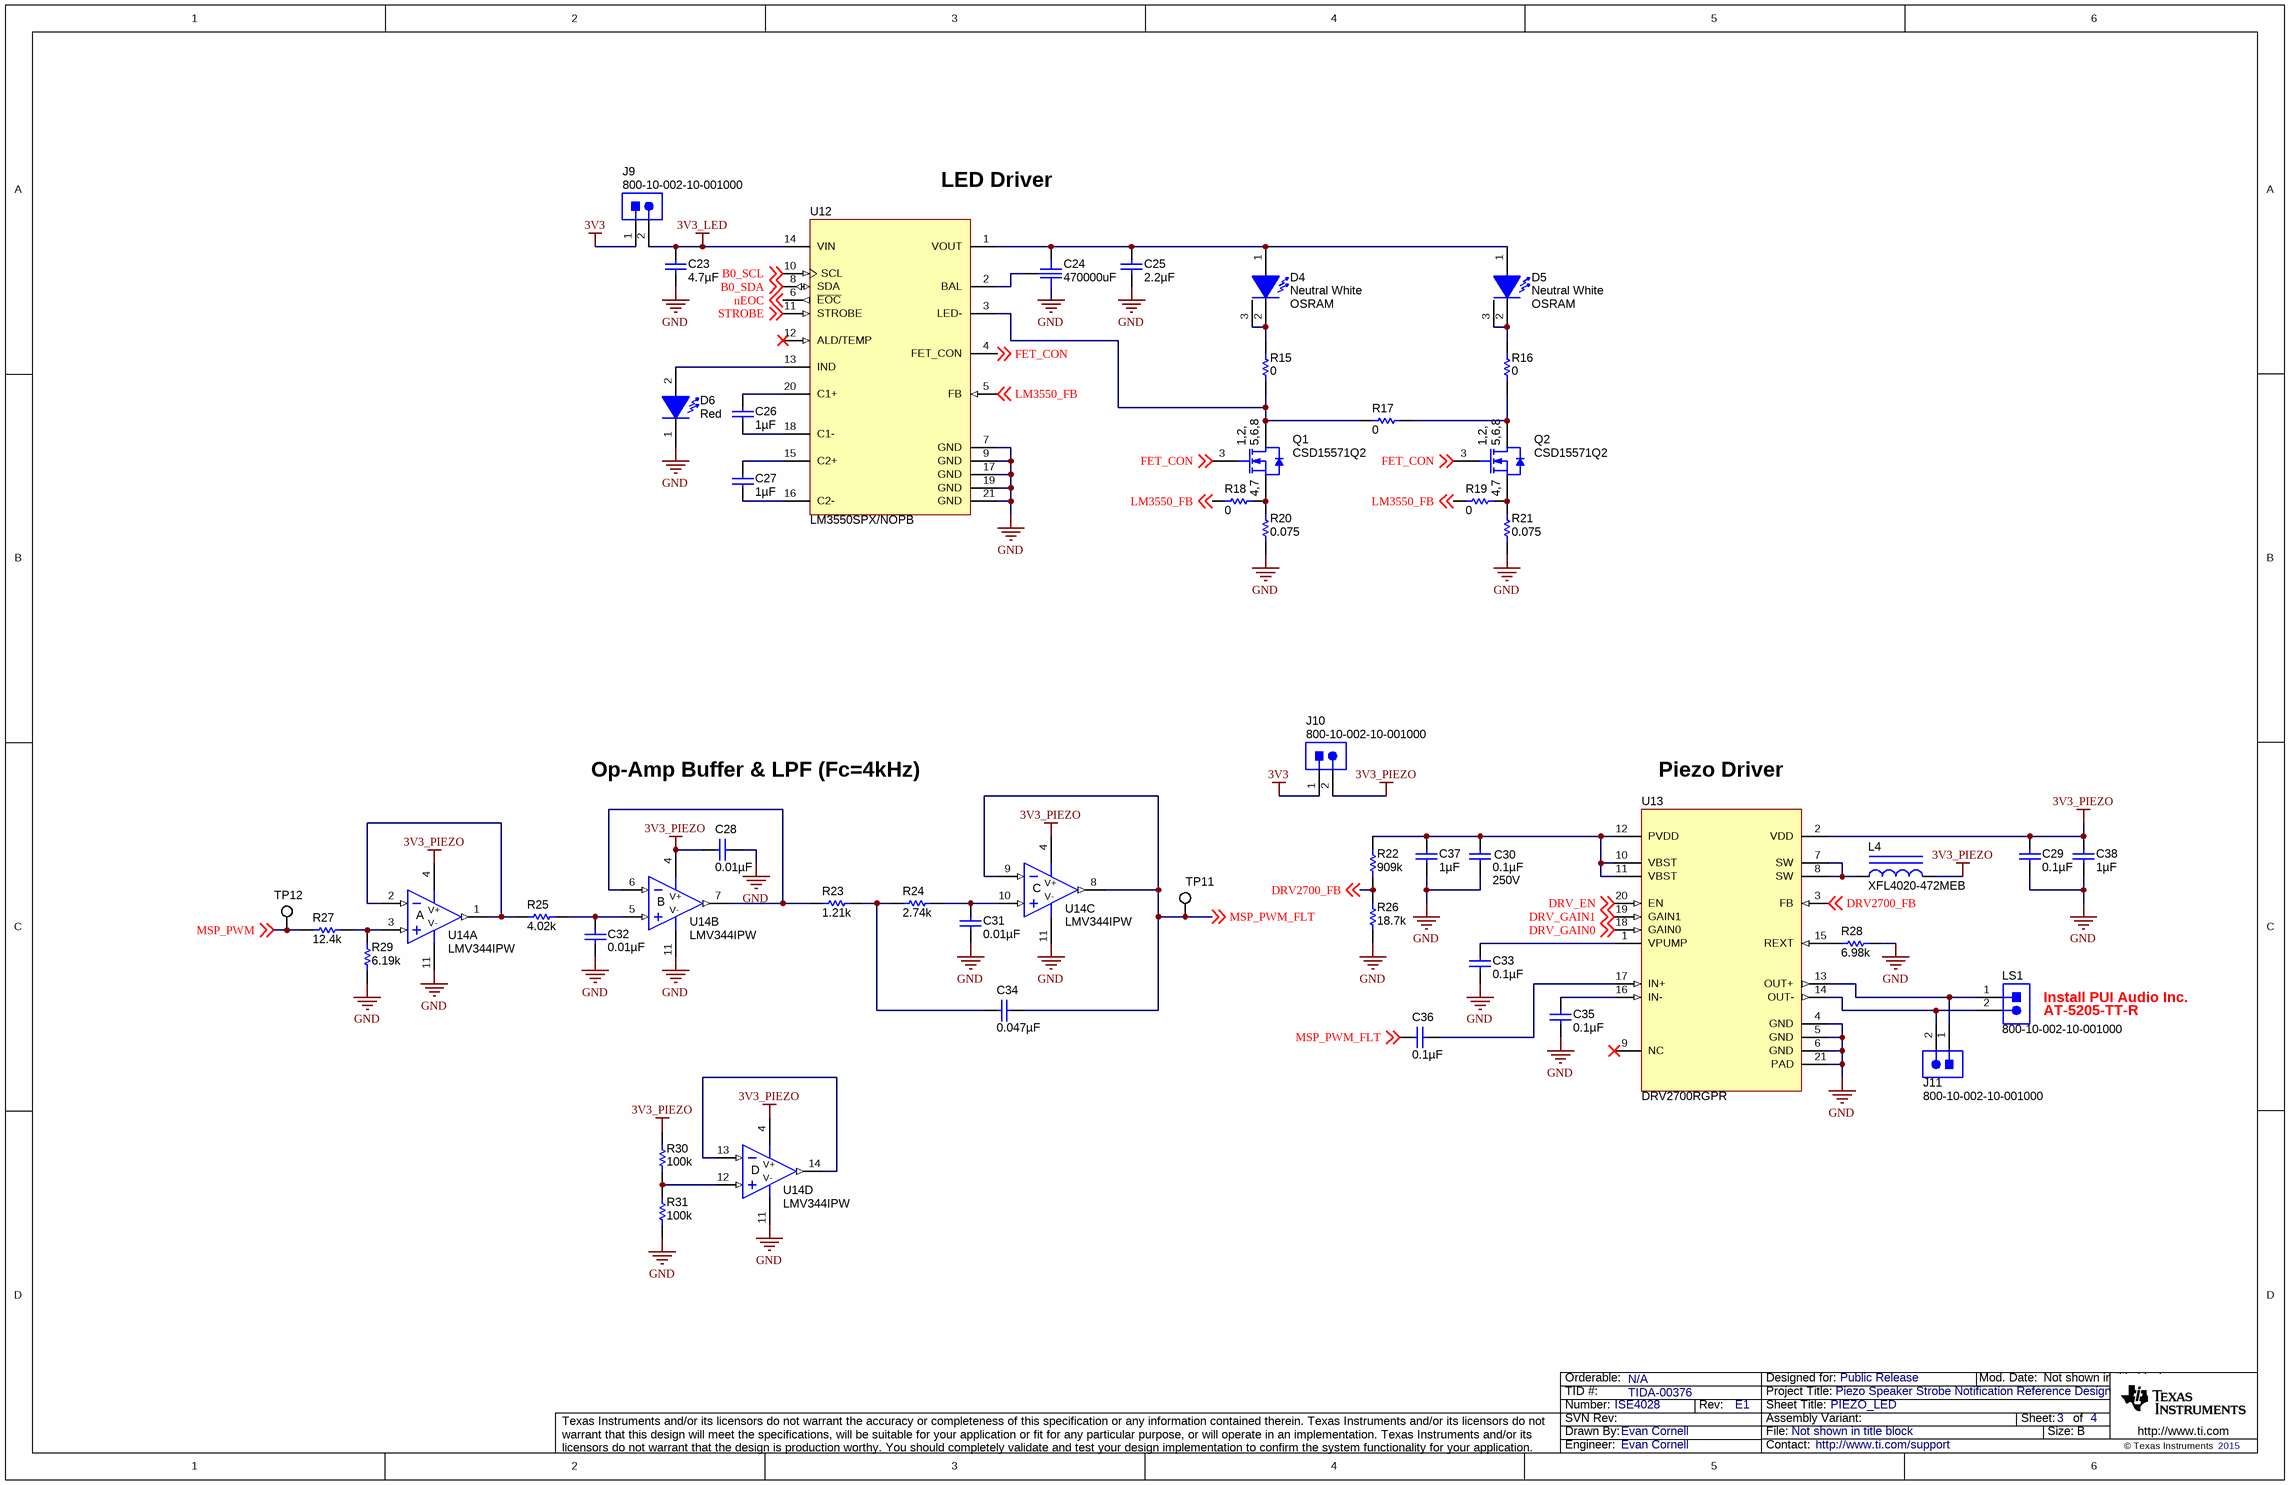
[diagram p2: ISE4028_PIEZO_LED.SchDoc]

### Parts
C23  ValueDisplayed: 4.7µF  [0805_HV]  (hidden comment: C2012X7R1A475M)
C24  ValueDisplayed: 470000uF  [DMF_2100x1400]  (hidden comment: DMF3Z5R5H474M3DTA0)
C25  ValueDisplayed: 2.2µF  [0805_HV]  (hidden comment: C2012X7R1C225K)
C26  ValueDisplayed: 1µF  [0603]  (hidden comment: C1608X7R1C105K)
C27  ValueDisplayed: 1µF  [0603]  (hidden comment: C1608X7R1C105K)
C28  ValueDisplayed: 0.01µF  [0402]  (hidden comment: C1005X7R1C103K)
C29  ValueDisplayed: 0.1µF  [0402]  (hidden comment: C1005X7R1H104K)
C30  ValueDisplayed: 0.1µF  Value2: 250V  [1206]  (hidden comment: C3216X7R2E104K)
C31  ValueDisplayed: 0.01µF  [0402]  (hidden comment: C1005X7R1C103K)
C32  ValueDisplayed: 0.01µF  [0402]  (hidden comment: C1005X7R1C103K)
C33  ValueDisplayed: 0.1µF  [0402]  (hidden comment: C1005X7R1H104K)
C34  ValueDisplayed: 0.047µF  [0402]  (hidden comment: C1005X7R1C473K)
C35  ValueDisplayed: 0.1µF  [0402]  (hidden comment: C1005X7R1H104K)
C36  ValueDisplayed: 0.1µF  [0402]  (hidden comment: C1005X7R1H104K)
C37  ValueDisplayed: 1µF  [2220]  (hidden comment: GRM55DR72E105KW01L)
C38  ValueDisplayed: 1µF  [0603]  (hidden comment: C1608X7R1C105K)
D4  value Neutral White  Manufacturer: OSRAM  [GW CSSRM1_PC_White]  (hidden comment: GW CSSRM1.PC-MTNP-5L7N-1)
D5  value Neutral White  Manufacturer: OSRAM  [GW CSSRM1_PC_White]  (hidden comment: GW CSSRM1.PC-MTNP-5L7N-1)
D6  value Red  [SML-P1_RED]  (hidden comment: SML-P12UTT86)
J9  800-10-002-10-001000  [Mill-Max_800-10-002-10-001000]
J10  800-10-002-10-001000  [Mill-Max_800-10-002-10-001000]
J11  800-10-002-10-001000  [Mill-Max_800-10-002-10-001000]
L4  XFL4020-472MEB  [XFL4020]
LS1  800-10-002-10-001000  [Mill-Max_800-10-002-10-001000]
Q1  CSD15571Q2  [TRANS_NexFET_Q2]
Q2  CSD15571Q2  [TRANS_NexFET_Q2]
R15  ValueDisplayed: 0  [2512]  (hidden comment: CRCW25120000Z0EG)
R16  ValueDisplayed: 0  [2512]  (hidden comment: CRCW25120000Z0EG)
R17  ValueDisplayed: 0  [0603]  (hidden comment: CRCW06030000Z0EA)
R18  ValueDisplayed: 0  [0402]  (hidden comment: CRCW04020000Z0ED)
R19  ValueDisplayed: 0  [0402]  (hidden comment: CRCW04020000Z0ED)
R20  ValueDisplayed: 0.075  [1206]  (hidden comment: CSR1206FK75L0)
R21  ValueDisplayed: 0.075  [1206]  (hidden comment: CSR1206FK75L0)
R22  ValueDisplayed: 909k  [0402]  (hidden comment: CRCW0402909KFKED)
R23  ValueDisplayed: 1.21k  [0402]  (hidden comment: CRCW04021K21FKED)
R24  ValueDisplayed: 2.74k  [0402]  (hidden comment: CRCW04022K74FKED)
R25  ValueDisplayed: 4.02k  [0402]  (hidden comment: CRCW04024K02FKED)
R26  ValueDisplayed: 18.7k  [0402]  (hidden comment: CRCW040218K7FKED)
R27  ValueDisplayed: 12.4k  [0402]  (hidden comment: CRCW040212K4FKED)
R28  ValueDisplayed: 6.98k  [0402]  (hidden comment: CRCW04026K98FKED)
R29  ValueDisplayed: 6.19k  [0402]  (hidden comment: CRCW04026K19FKED)
R30  ValueDisplayed: 100k  [0402]  (hidden comment: CRCW0402100KFKED)
R31  ValueDisplayed: 100k  [0402]  (hidden comment: CRCW0402100KFKED)
TP11  5002  [Keystone5002]  (value not drawn)
TP12  5002  [Keystone5002]  (value not drawn)
U12  LM3550SPX/NOPB  [NHU0020A]
U13  DRV2700RGPR  [RGP0020D]
U14  LMV344IPW  [PW0014A_N]  (parts A,B,C,D of 4)

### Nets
3V3: J9.1 J10.1
3V3_LED: C23.1 J9.2 U12.14(VIN)
3V3_PIEZO: C28.1 C29.2 C38.1 J10.2 L4.2 R30.2 U13.2(VDD) U14.4(V+)
GND: C23.2 C24.2 C25.2 C28.2 C29.1 C30.2 C31.2 C32.2 C33.1 C35.2 C37.2 C38.2 D6.1(K) R20.1 R21.1 R26.1 R28.1 R29.1 R31.1 U12.7(GND) U12.9(GND) U12.17(GND) U12.19(GND) U12.21(GND) U13.4(GND) U13.5(GND) U13.6(GND) U13.21(PAD) U14.11(V-)
B0_SCL: U12.10(SCL) ; off-sheet B0_SCL
B0_SDA: U12.8(SDA) ; off-sheet B0_SDA
DRV2700_FB: R22.1 R26.2 U13.3(FB) ; off-sheet DRV2700_FB
DRV_EN: U13.20(EN) ; off-sheet DRV_EN
DRV_GAIN0: U13.18(GAIN0) ; off-sheet DRV_GAIN0
DRV_GAIN1: U13.19(GAIN1) ; off-sheet DRV_GAIN1
FET_CON: Q1.3(G) Q2.3(G) U12.4(FET_CON) ; off-sheet FET_CON
LM3550_FB: R18.1 R19.1 U12.5(FB) ; off-sheet LM3550_FB
MSP_PWM: R27.1 TP12.1 ; off-sheet MSP_PWM
MSP_PWM_FLT: C34.1 C36.2 TP11.1 U14.8(OUT) U14.9(IN-) ; off-sheet MSP_PWM_FLT
nEOC: U12.6(~{EOC}) ; off-sheet nEOC
STROBE: U12.11(STROBE) ; off-sheet STROBE
NetC24_1: C24.1 C25.1 D4.1(A) D5.1(A) U12.1(VOUT)
NetC24_3: C24.3 U12.2(BAL)
NetC26_1: C26.1 U12.20(C1+)
NetC26_2: C26.2 U12.18(C1-)
NetC27_1: C27.1 U12.15(C2+)
NetC27_2: C27.2 U12.16(C2-)
NetC30_1: C30.1 C37.1 R22.2 U13.10(VBST) U13.11(VBST) U13.12(PVDD)
NetC31_1: C31.1 R24.2 U14.10(IN+)
NetC32_1: C32.1 R25.2 U14.5(IN+)
NetC33_2: C33.2 U13.1(VPUMP)
NetC34_2: C34.2 R23.2 R24.1
NetC35_1: C35.1 U13.16(IN-)
NetC36_1: C36.1 U13.17(IN+)
NetD4_2: D4.2(K) D4.3(HEATSINK) R15.2
NetD5_2: D5.2(K) D5.3(HEATSINK) R16.2
NetD6_2: D6.2(A) U12.13(IND)
NetJ11_1: J11.1 LS1.1 U13.13(OUT+)
NetJ11_2: J11.2 LS1.2 U13.14(OUT-)
NetL4_1: L4.1 U13.7(SW) U13.8(SW)
NetQ1_1: Q1.1(D) Q1.2(D) Q1.5(D) Q1.6(D) Q1.8(D) R15.1 R17.1 U12.3(LED-)
NetQ1_4: Q1.4(S) Q1.7(S) R18.2 R20.2
NetQ2_1: Q2.1(D) Q2.2(D) Q2.5(D) Q2.6(D) Q2.8(D) R16.1 R17.2
NetQ2_4: Q2.4(S) Q2.7(S) R19.2 R21.2
NetR23_1: R23.1 U14.6(IN-) U14.7(OUT)
NetR25_1: R25.1 U14.1(OUT) U14.2(IN-)
NetR27_2: R27.2 R29.2 U14.3(IN+)
NetR28_2: R28.2 U13.15(REXT)
NetR30_1: R30.1 R31.2 U14.12(IN+)
NetU14_13: U14.13(IN-) U14.14(OUT)

Not connected (* = marked no-connect by the designer): U12 12(ALD/TEMP)*; U13 9(NC)*

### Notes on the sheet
- LED Driver
- Op-Amp Buffer & LPF (Fc=4kHz)
- Piezo Driver
- (near LS1) Install PUI Audio Inc.
- (near LS1) AT-5205-TT-R

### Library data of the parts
C23 = C2012X7R1A475M: CAP, CERM, 4.7 µF, 10 V, +/- 20%, X7R, 0805; Manufacturer: TDK; Polarized: N; CompType: Capacitor; Value: 4.7uF; U/M: EA; Cap_F: 0.0000047; Tolerance_%: 20; Value1: Unknown; VDC_V: 10; Value2: 10V; TaMin_C: -55; TaMax_C: 125; Cap_Case: 0805
C24 = DMF3Z5R5H474M3DTA0: CAP, Electric Double Layer, 470000uF, 4.2 V, +/- 20%, 0.045 ohm, Electrical  Double Layer Capacitor, Body 21.5x14.5mm, Pitch 3.5mm SMD; Manufacturer: MuRata; SymbolCreator: a0411947; U/M: EA; Cap_F: 0.47; Tolerance_%: 20; VDC_V: 4.2; Value2: 4.2V; ESR_ohm: 0.045; TaMin_C: -30; TaMax_C: 70; Polarized: Y; Cap_Case: 21x14mm
C25 = C2012X7R1C225K: CAP, CERM, 2.2 µF, 16 V, +/- 10%, X7R, 0805; Manufacturer: TDK; Polarized: N; CompType: Capacitor; Value: 2.2uF; U/M: EA; Cap_F: 0.0000022; Tolerance_%: 10; ESR_ohm: 0.0049; Value1: 0.0049 ohm; VDC_V: 16; Value2: 16V; TaMin_C: -55; TaMax_C: 125; Cap_Case: 0805
C26 C27 C38 = C1608X7R1C105K: CAP, CERM, 1 µF, 16 V, +/- 10%, X7R, 0603; Manufacturer: TDK; Polarized: N; CompType: Capacitor; Value: 1uF; U/M: EA; Cap_F: 0.000001; Tolerance_%: 10; ESR_ohm: 0.0057; Value1: 0.0057 ohm; VDC_V: 16; Value2: 16V; TaMin_C: -55; TaMax_C: 125
C28 C31 C32 = C1005X7R1C103K: CAP, CERM, 0.01 µF, 16 V, +/- 10%, X7R, 0402; Manufacturer: TDK; Polarized: N; CompType: Capacitor; Value: 0.01uF; U/M: EA; Cap_F: 0.00000001; Tolerance_%: 10; ESR_ohm: 0.0623; Value1: 0.0623 ohm; VDC_V: 16; Value2: 16V; TaMin_C: -55; TaMax_C: 125
C29 C33 C35 C36 = C1005X7R1H104K: as C1 on sheet ISE4028_PWR_MCU
C30 = C3216X7R2E104K: CAP, CERM, 0.1 µF, 250 V, +/- 10%, X7R, 1206; Manufacturer: TDK; Polarized: N; CompType: Capacitor; Value: 0.1uF; U/M: EA; Cap_F: 0.0000001; Tolerance_%: 10; ESR_ohm: 0.0217; Value1: 0.0217 ohm; VDC_V: 250; TaMin_C: -55; TaMax_C: 125
C34 = C1005X7R1C473K: CAP, CERM, 0.047 µF, 16 V, +/- 10%, X7R, 0402; Manufacturer: TDK; Polarized: N; CompType: Capacitor; Value: 0.047uF; U/M: EA; Cap_F: 0.000000047; Tolerance_%: 10; ESR_ohm: 0.0305; Value1: 0.0305 ohm; VDC_V: 16; Value2: 16V; TaMin_C: -55; TaMax_C: 125
C37 = GRM55DR72E105KW01L: CAP, CERM, 1 µF, 250 V, +/- 10%, X7R, 2220; Manufacturer: MuRata; Polarized: N; CompType: Capacitor; Value: 1uF; U/M: EA; Cap_F: 0.000001; Tolerance_%: 10; Value1: Unknown; VDC_V: 250; Value2: 250V; TaMin_C: -55; TaMax_C: 125
D4 D5 = GW CSSRM1.PC-MTNP-5L7N-1: LED, Neutral White, SMD; SymbolCreator: a0412235; Vf_V: 2.85; Value2: 2.85V; Io_A: 0.7; Vr_V: 1.2; Ir_A: 0.02; Tjmax_C: 135; Value1: W; Angle: 120; U/M: EA
D6 = SML-P12UTT86: LED, Red, SMD; Manufacturer: Rohm; Type: AlInGaP; Vf_V: 2; Value2: 2V; Io_A: 0.02; Value1: W; U/M: EA
J9-J11 LS1 = 800-10-002-10-001000: as J1 on sheet ISE4028_PWR_MCU
L4 = XFL4020-472MEB: Inductor, Shielded, Composite, 4.7 µH, 2.7 A, 0.05 ohm, SMD; Manufacturer: Coilcraft; Value: 4.7uH; Ind_H: 4.7E-6; ValueDisplayed: 4.7µH; Imax_A: 2.7; Irms: 5A @ 40C rise; Isat: 2.7A @ 30% inductance drop; DCR_ohm: 0.05; Value2: 2.7A
Q1 Q2 = CSD15571Q2: MOSFET, N-CH, 20 V, 10 A, SON 2x2mm; Manufacturer: Texas Instruments; Alternate Manufacturer: None; U/M: EA; ChType: N; Value: 20V; VdsMax_V: 20; Value1: 19.2 ohm; Rdson45_ohm: 19.2; Value2: 2.5 nC; QgTyp_nC: 2.5; IdsMax_A: 10
R15 R16 = CRCW25120000Z0EG: RES, 0, 5%, 1 W, 2512; Manufacturer: Vishay-Dale; CompType: Resistor; Value: 0; Value_Code: 0000; Tolerance_%: 5; Power_W: 1; Value2: 1W; TempCo: ppm/C; EIA_Code: E24; U/M: EA
R17 = CRCW06030000Z0EA: RES, 0, 5%, 0.1 W, 0603; Manufacturer: Vishay-Dale; CompType: Resistor; Value: 0; Value_Code: 0000; Tolerance_%: 5; Power_W: 0.1; Value2: 0.1W; VDC_V: 75; TempCo: 200 ppm/C; EIA_Code: E24; U/M: EA
R18 R19 = CRCW04020000Z0ED: RES, 0, 5%, 0.063 W, 0402; Manufacturer: Vishay-Dale; CompType: Resistor; Value: 0; Value_Code: 0000; Tolerance_%: 5; Power_W: 0.063; Value2: 0.063W; VDC_V: 50; TempCo: 200 ppm/C; EIA_Code: E24; U/M: EA
R20 R21 = CSR1206FK75L0: RES, 0.075, 1%, 0.5 W, 1206; Manufacturer: Stackpole Electronics Inc; CompType: Resistor; Value: 0.075; Value_Code: R075; Tolerance_%: 1; Power_W: 0.5; Value2: 0.5W; TempCo: 100 ppm/C; EIA_Code: E96; U/M: EA
R22 = CRCW0402909KFKED: RES, 909 k, 1%, 0.063 W, 0402; Manufacturer: Vishay-Dale; CompType: Resistor; Value: 909k; Res_ohm: 909000; Tolerance_%: 1; Power_W: 0.063; Value2: 0.063W; VDC_V: 50; TempCo: 100 ppm/C; EIA_Code: E96; U/M: EA
R23 = CRCW04021K21FKED: RES, 1.21 k, 1%, 0.063 W, 0402; Manufacturer: Vishay-Dale; CompType: Resistor; Value: 1.21k; Res_ohm: 1210; Value_Code: 1k21; Tolerance_%: 1; Power_W: 0.063; Value2: 0.063W; VDC_V: 50; TempCo: 100 ppm/C; EIA_Code: E96; U/M: EA
R24 = CRCW04022K74FKED: RES, 2.74 k, 1%, 0.063 W, 0402; Manufacturer: Vishay-Dale; CompType: Resistor; Value: 2.74k; Res_ohm: 2740; Value_Code: 2k74; Tolerance_%: 1; Power_W: 0.063; Value2: 0.063W; VDC_V: 50; TempCo: 100 ppm/C; EIA_Code: E96; U/M: EA
R25 = CRCW04024K02FKED: RES, 4.02 k, 1%, 0.063 W, 0402; Manufacturer: Vishay-Dale; CompType: Resistor; Value: 4.02k; Res_ohm: 4020; Value_Code: 4k02; Tolerance_%: 1; Power_W: 0.063; Value2: 0.063W; VDC_V: 50; TempCo: 100 ppm/C; EIA_Code: E96; U/M: EA
R26 = CRCW040218K7FKED: RES, 18.7 k, 1%, 0.063 W, 0402; Manufacturer: Vishay-Dale; CompType: Resistor; Value: 18.7k; Res_ohm: 18700; Value_Code: 18k7; Tolerance_%: 1; Power_W: 0.063; Value2: 0.063W; VDC_V: 50; TempCo: 100 ppm/C; EIA_Code: E96; U/M: EA
R27 = CRCW040212K4FKED: RES, 12.4 k, 1%, 0.063 W, 0402; Manufacturer: Vishay-Dale; CompType: Resistor; Value: 12.4k; Res_ohm: 12400; Value_Code: 12k4; Tolerance_%: 1; Power_W: 0.063; Value2: 0.063W; VDC_V: 50; TempCo: 100 ppm/C; EIA_Code: E96; U/M: EA
R28 = CRCW04026K98FKED: RES, 6.98 k, 1%, 0.063 W, 0402; Manufacturer: Vishay-Dale; CompType: Resistor; Value: 6.98k; Res_ohm: 6980; Value_Code: 6k98; Tolerance_%: 1; Power_W: 0.063; Value2: 0.063W; VDC_V: 50; TempCo: 100 ppm/C; EIA_Code: E96; U/M: EA
R29 = CRCW04026K19FKED: RES, 6.19 k, 1%, 0.063 W, 0402; Manufacturer: Vishay-Dale; CompType: Resistor; Value: 6.19k; Res_ohm: 6190; Value_Code: 6k19; Tolerance_%: 1; Power_W: 0.063; Value2: 0.063W; VDC_V: 50; TempCo: 100 ppm/C; EIA_Code: E96; U/M: EA
R30 R31 = CRCW0402100KFKED: as R8 on sheet ISE4028_PWR_MCU
TP11 TP12 = 5002: Test Point, Miniature, White, TH; Manufacturer: Keystone; CompType: Test Point Loop; U/M: EA
U12 = LM3550SPX/NOPB: 5A Flash LED Driver with Automatic VLED and ESR Detection for Mobile Camera Systems, NHU0020A; Alternate PartNumber: LM3550SP/NOPB; Manufacturer: Texas Instruments; SymbolCreator: Altium; CompType: IC; U/M: EA
U13 = DRV2700RGPR: Piezo Driver with Integrated Boost Converter, RGP0020D; Alternate PartNumber: DRV2700RGPT; Manufacturer: Texas Instruments; SymbolCreator: Altium; CompType: IC; U/M: EA
U14 = LMV344IPW: R-R Out Quad Op Amp, PW0014A; Manufacturer: Texas Instruments; SymbolCreator: a0412235; CompType: OpAmp IC

## Sheet ISE4028_TID_Hardware.SchDoc: Hardware
size 431 x 279 mm; Date: Not shown in title block; ApprovedBy: Not shown in title block; CheckedBy: Not shown in title block; Author: Not shown in title block; CompanyName: Not shown in title block; DrawnBy: Evan Cornell; Engineer: Not shown in title block; Organization: Not shown in title block; Address1: Not shown in title block; Address2: Not shown in title block; Address3: Not shown in title block; Address4: Not shown in title block; DocumentNumber: 4; Revision: Use project parameter SCH_Rev; SheetNumber: 4; SheetTotal: 4; PageSetup: Record=PageOptions¦CenterHorizontal=True¦CenterVertical=True¦PrintScale=1.00¦XCorrection=1.00¦YCorrection=1.00¦PrintKind=0¦BorderSize=5000000¦LeftOffset=0¦BottomOffset=0¦Orientation=2¦PaperLength=1000¦PaperWidth=1000¦Scale=100¦PaperSource=15¦PrintQuality=600¦MediaType=1¦DitherType=10¦PaperKind=Letter¦PrintScaleMode=1
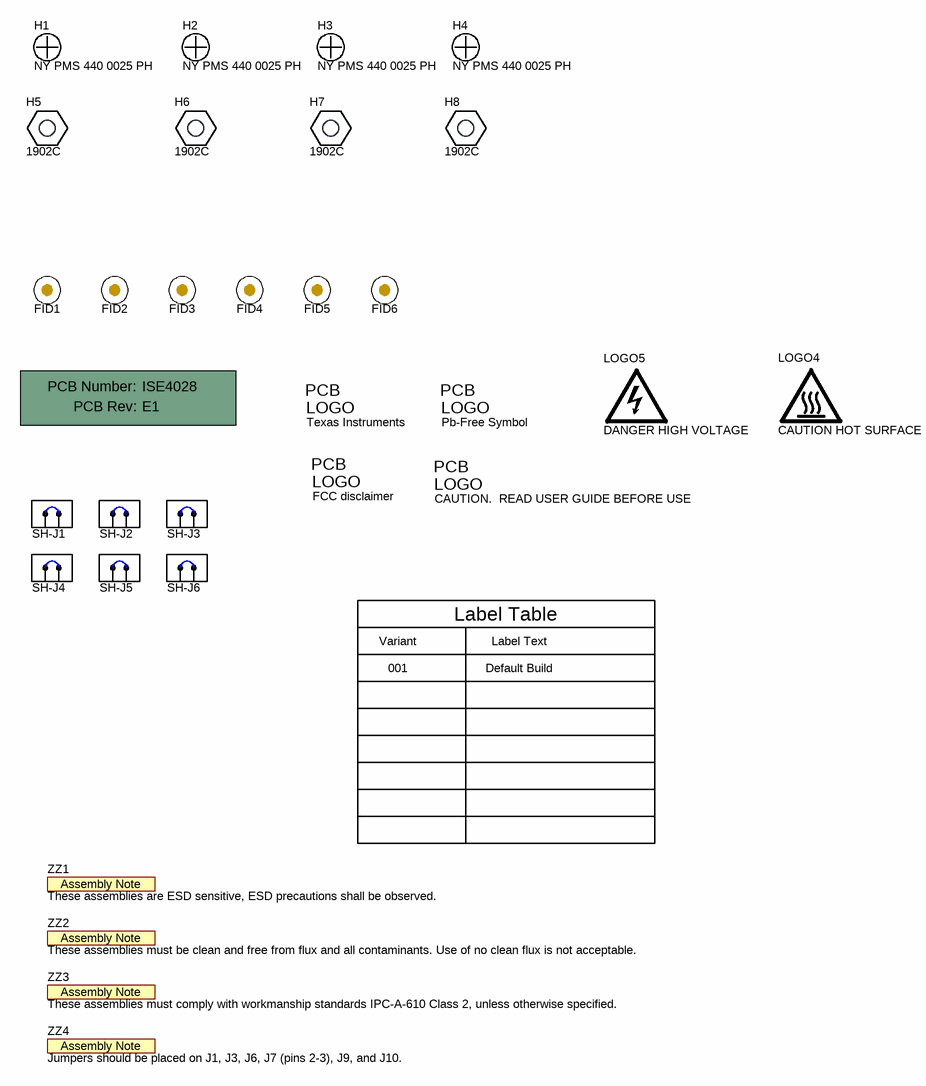
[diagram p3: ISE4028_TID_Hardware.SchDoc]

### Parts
!PCB1  Printed Circuit Board  (value not drawn)  (mechanical)
FID1  Fiducial  [Fiducial10-20]  (value not drawn)
FID2  Fiducial  [Fiducial10-20]  (value not drawn)
FID3  Fiducial  [Fiducial10-20]  (value not drawn)
FID4  Fiducial  [Fiducial10-20]  (value not drawn)
FID5  Fiducial  [Fiducial10-20]  (value not drawn)
FID6  Fiducial  [Fiducial10-20]  (value not drawn)
H1  NY PMS 440 0025 PH  [NY PMS 440 0025 PH]
H2  NY PMS 440 0025 PH  [NY PMS 440 0025 PH]
H3  NY PMS 440 0025 PH  [NY PMS 440 0025 PH]
H4  NY PMS 440 0025 PH  [NY PMS 440 0025 PH]
H5  1902C  [Keystone_1902C]
H6  1902C  [Keystone_1902C]
H7  1902C  [Keystone_1902C]
H8  1902C  [Keystone_1902C]
Logo1  Texas Instruments  [TI_Stacked_Overlay_Small]  (no BOM)
Logo2  Pb-Free Symbol  [Pb-Free_Overlay_Small]  (no BOM)
Logo3  FCC disclaimer  [FCC_disclaimer_stacked]  (no BOM)
LOGO4  CAUTION HOT SURFACE  [IEC_HotSurface_Small]  (no BOM)
LOGO5  DANGER HIGH VOLTAGE  [IEC_HighVoltage_Small]  (no BOM)
Logo6  CAUTION.  READ USER GUIDE BEFORE USE  [IEC_Caution_Small]  (no BOM)
SH-J1  881545-2  [TE_881545-2]  (value not drawn)  (mechanical)
SH-J2  881545-2  [TE_881545-2]  (value not drawn)  (mechanical)
SH-J3  881545-2  [TE_881545-2]  (value not drawn)  (mechanical)
SH-J4  881545-2  [TE_881545-2]  (value not drawn)  (mechanical)
SH-J5  881545-2  [TE_881545-2]  (value not drawn)  (mechanical)
SH-J6  881545-2  [TE_881545-2]  (value not drawn)  (mechanical)
ZZ1  These assemblies are ESD sensitive, ESD precautions shall be observed.  [AssemblyNote]  (no BOM)
ZZ2  These assemblies must be clean and free from flux and all contaminants. Use of no clean flux is not acceptable.  [AssemblyNote]  (no BOM)
ZZ3  These assemblies must comply with workmanship standards IPC-A-610 Class 2, unless otherwise specified.  [AssemblyNote]  (no BOM)
ZZ4  Jumpers should be placed on J1, J3, J6, J7 (pins 2-3), J9, and J10.  [AssemblyNote]  (no BOM)

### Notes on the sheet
- Variant
- Label Table
- Label Text
- 001
- Default Build

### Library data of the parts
!PCB1 = PCB: Manufacturer: Any; PartNumber: ISE4028; SymbolCreator: a0412235
FID1-FID6 = Fiducial: Fiducial mark.  There is nothing to buy or mount.; SymbolCreator: codlsc
H1-H4 = NY PMS 440 0025 PH: Machine Screw, Round, #4-40 x 1/4, Nylon, Philips panhead; Manufacturer: B&F Fastener Supply; CompType: Hardware; SymbolCreator: codlsc; U/M: EA
H5-H8 = 1902C: Standoff, Hex, 0.5"L #4-40 Nylon; Manufacturer: Keystone; CompType: Hardware
Logo1 = TI_Logo: Texas Instrument Corporate Signature; SymbolCreator: codlsc
Logo2 = Pb-Free: SymbolCreator: a0412235
Logo3 = FCC_disclaimer: SymbolCreator: codlsc
LOGO4 = IEC_HotSurface: IEC 61010-1 Hot Surface Warning; SymbolCreator: a0412235
LOGO5 = IEC_HighVoltage: IEC 61010-1 High Voltage Warning; SymbolCreator: a0412235
Logo6 = IEC_Caution: IEC 61010-1 Caution Warning; SymbolCreator: a0412235
SH-J1-SH-J6 = 881545-2: Shunt, 100mil, Gold plated, Black; Manufacturer: TE Connectivity
ZZ1-ZZ4 = AssemblyNote: SymbolCreator: codlsc

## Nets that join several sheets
3V3: ISE4028_PWR_MCU (J1.2 J6.1), ISE4028_PIEZO_LED (J9.1 J10.1)
GND: ISE4028_PWR_MCU (59 pins), ISE4028_PIEZO_LED (29 pins)
B0_SCL: ISE4028_PWR_MCU (R4.1 TP4.1 U2.32), ISE4028_PIEZO_LED (U12.10)
B0_SDA: ISE4028_PWR_MCU (R5.1 TP3.1 U2.31), ISE4028_PIEZO_LED (U12.8)
DRV_EN: ISE4028_PWR_MCU (U2.4), ISE4028_PIEZO_LED (U13.20)
DRV_GAIN0: ISE4028_PWR_MCU (U2.6), ISE4028_PIEZO_LED (U13.18)
DRV_GAIN1: ISE4028_PWR_MCU (U2.5), ISE4028_PIEZO_LED (U13.19)
MSP_PWM: ISE4028_PWR_MCU (R32.2), ISE4028_PIEZO_LED (R27.1 TP12.1)
nEOC: ISE4028_PWR_MCU (R9.1 U2.29), ISE4028_PIEZO_LED (U12.6)
STROBE: ISE4028_PWR_MCU (R12.2 U2.30), ISE4028_PIEZO_LED (U12.11)

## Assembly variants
001: not fitted FID1 FID2 FID3 FID4 FID5 FID6 J11 LS1 R17 R19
